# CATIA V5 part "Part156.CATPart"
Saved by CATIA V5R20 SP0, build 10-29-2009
Part number: 9FA 105712
Revision: ANY
Definition: UNKNOWN
Nomenclature: 9FA 105712
Source: Unknown
Bounding box of the stored display mesh (mm): x -5 to 5, y -10 to 10, z -5 to 5
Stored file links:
  C:\Users\Utente\Desktop\IO LAVORO\3D X SITO CF\CUMSA\3D files FA\FA 105712-20\Part156.CATPart
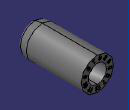
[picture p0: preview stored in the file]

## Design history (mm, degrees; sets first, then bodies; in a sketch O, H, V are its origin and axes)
Set1 "FacciaKO#NONE#9152"
  DatumSurface1 "Sup9152_1"
  DatumCurve1 "Crv9152_1"
Body1 "Cortar-Extruir5" (main body)
  Solid1: solid without history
